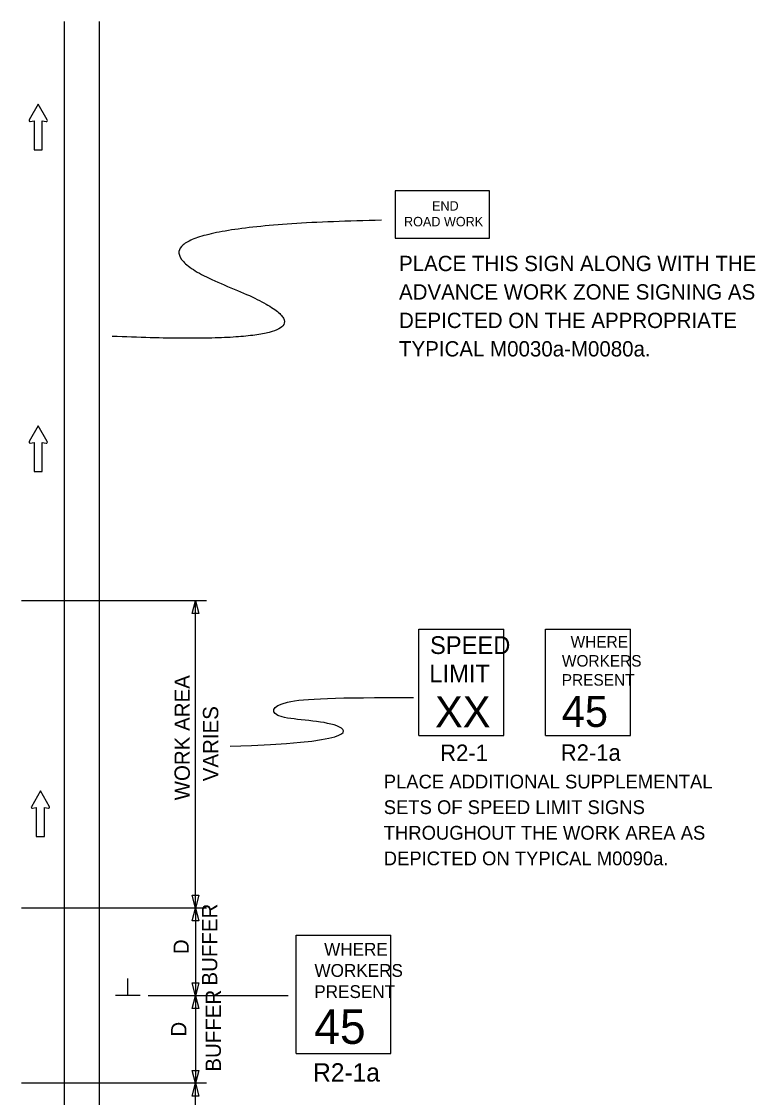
# Model space of a CAD drawing. Extents: x 16730 to 18475, y 5651 to 6927.
# Drawn here: x 17063.9 to 17399.4, y 6401.4 to 6893.1 of the extents above; entities that cross this region are included whole.
import ezdxf

# ---------------------------------------------------------------- set-up
doc = ezdxf.new("R2010")
doc.units = 0
for name, color, linetype in [('Level 6', 7, 'Continuous'), ('MT_SCRATCH_LEVEL_E', 7, 'Continuous'), ('PAVT_EDGE_EX', 7, 'Continuous'), ('TRAFFIC_SIGNS_PR', 7, 'Continuous'), ('TYPICAL_TEXT_DIMEN_PR', 7, 'Continuous')]:
    doc.layers.add(name, color=color, linetype=linetype)

msp = doc.modelspace()

# ---------------------------------------------------------------- linework, layer by layer
at = {"layer": 'Level 6'}
for p, q in [((17189.51, 6475.56), (17232.71, 6475.56)), ((17189.51, 6421.56), (17189.51, 6475.56)), ((17232.71, 6421.56), (17232.71, 6475.56)), ((17189.51, 6421.56), (17232.71, 6421.56))]:
    msp.add_line(p, q, dxfattribs=at)
at = {"layer": 'MT_SCRATCH_LEVEL_E'}
for p, q in [((17071.54, 6855.34), (17067.43, 6848.1)), ((17071.54, 6855.34), (17067.43, 6848.1)), ((17075.69, 6848.1), (17071.54, 6855.34)), ((17075.69, 6848.1), (17071.54, 6855.34)), ((17067.91, 6847.41), (17069.69, 6847.73)), ((17067.91, 6847.41), (17069.69, 6847.73)), ((17069.69, 6847.73), (17069.69, 6834.47)), ((17069.69, 6847.73), (17069.69, 6834.47)), ((17073.43, 6834.47), (17073.43, 6847.73)), ((17073.43, 6847.73), (17075.21, 6847.41)), ((17073.43, 6834.47), (17073.43, 6847.73)), ((17073.43, 6847.73), (17075.21, 6847.41)), ((17069.69, 6834.47), (17073.43, 6834.47)), ((17069.69, 6834.47), (17073.43, 6834.47)), ((17071.54, 6708.37), (17067.43, 6701.13)), ((17071.54, 6708.37), (17067.43, 6701.13)), ((17075.69, 6701.13), (17071.54, 6708.37)), ((17075.69, 6701.13), (17071.54, 6708.37)), ((17067.91, 6700.45), (17069.69, 6700.76)), ((17067.91, 6700.45), (17069.69, 6700.76)), ((17069.69, 6700.76), (17069.69, 6687.51)), ((17069.69, 6700.76), (17069.69, 6687.51)), ((17073.43, 6687.51), (17073.43, 6700.76)), ((17073.43, 6700.76), (17075.21, 6700.45)), ((17073.43, 6687.51), (17073.43, 6700.76)), ((17073.43, 6700.76), (17075.21, 6700.45)), ((17069.69, 6687.51), (17073.43, 6687.51)), ((17069.69, 6687.51), (17073.43, 6687.51)), ((17072.54, 6541.51), (17068.43, 6534.27)), ((17072.54, 6541.51), (17068.43, 6534.27)), ((17076.69, 6534.27), (17072.54, 6541.51)), ((17076.69, 6534.27), (17072.54, 6541.51)), ((17068.91, 6533.59), (17070.69, 6533.91)), ((17068.91, 6533.59), (17070.69, 6533.91)), ((17070.69, 6533.91), (17070.69, 6520.65)), ((17070.69, 6533.91), (17070.69, 6520.65)), ((17074.43, 6520.65), (17074.43, 6533.91)), ((17074.43, 6533.91), (17076.21, 6533.59)), ((17074.43, 6520.65), (17074.43, 6533.91)), ((17074.43, 6533.91), (17076.21, 6533.59)), ((17070.69, 6520.65), (17074.43, 6520.65)), ((17070.69, 6520.65), (17074.43, 6520.65))]:
    msp.add_line(p, q, dxfattribs=at)
for centre, start, end in [((17067.84, 6847.87), 150.4248, 279.9638), ((17067.84, 6847.87), 150.4248, 279.9638), ((17075.28, 6847.87), 260.0362, 29.7731), ((17075.28, 6847.87), 260.0362, 29.7731), ((17067.84, 6700.91), 150.4248, 279.9638), ((17067.84, 6700.91), 150.4248, 279.9638), ((17075.28, 6700.91), 260.0362, 29.7731), ((17075.28, 6700.91), 260.0362, 29.7731), ((17068.84, 6534.05), 150.4248, 279.9638), ((17068.84, 6534.05), 150.4248, 279.9638), ((17076.28, 6534.05), 260.0362, 29.7731), ((17076.28, 6534.05), 260.0362, 29.7731)]:
    msp.add_arc(centre, 0.463, start, end, dxfattribs=at)
at = {"layer": 'PAVT_EDGE_EX'}
for p, q in [((17083.43, 6893.09), (17083.43, 6095.81)), ((17099.43, 6893.09), (17099.43, 6095.81))]:
    msp.add_line(p, q, dxfattribs=at)
at = {"layer": 'TRAFFIC_SIGNS_PR'}
for p, q in [((17245.53, 6615.35), (17284.41, 6615.35)), ((17245.53, 6566.75), (17245.53, 6615.35)), ((17284.41, 6566.75), (17284.41, 6615.35)), ((17303.44, 6615.44), (17342.32, 6615.44)), ((17303.44, 6566.84), (17303.44, 6615.44)), ((17342.32, 6566.84), (17342.32, 6615.44)), ((17245.53, 6566.75), (17284.41, 6566.75)), ((17303.44, 6566.84), (17342.32, 6566.84))]:
    msp.add_line(p, q, dxfattribs=at)
msp.add_lwpolyline([(17234.69, 6794.16), (17277.89, 6794.16), (17277.89, 6815.76), (17234.69, 6815.76)], close=True, dxfattribs=at)
msp.add_open_spline([(17228.4, 6802.25), (17089.56, 6799.6), (17228.53, 6743.73), (17105.43, 6749.22)], degree=2, dxfattribs=at)
at = {"layer": 'TYPICAL_TEXT_DIMEN_PR'}
for p, q in [((17148.43, 6628.39), (17063.94, 6628.39)), ((17141.86, 6622.53), (17143.43, 6628.39)), ((17143.43, 6487.93), (17143.43, 6628.39)), ((17143.43, 6628.39), (17145, 6622.53)), ((17143.43, 6622.53), (17141.86, 6622.53)), ((17145, 6622.53), (17143.43, 6622.53)), ((17143.43, 6487.93), (17141.86, 6493.79)), ((17141.86, 6493.79), (17143.43, 6493.79)), ((17143.43, 6493.79), (17145, 6493.79)), ((17145, 6493.79), (17143.43, 6487.93)), ((17148.43, 6487.93), (17063.94, 6487.93)), ((17141.86, 6482.07), (17143.43, 6487.93)), ((17143.43, 6487.93), (17143.43, 6447.93)), ((17143.43, 6487.93), (17145, 6482.07)), ((17143.43, 6482.07), (17141.86, 6482.07)), ((17145, 6482.07), (17143.43, 6482.07)), ((17112.56, 6447.94), (17112.56, 6455.72)), ((17143.43, 6447.93), (17141.86, 6453.79)), ((17141.86, 6453.79), (17143.43, 6453.79)), ((17143.43, 6453.79), (17145, 6453.79)), ((17145, 6453.79), (17143.43, 6447.93)), ((17118.18, 6447.94), (17106.93, 6447.94)), ((17185.75, 6447.93), (17121.85, 6447.93)), ((17141.86, 6442.07), (17143.43, 6447.93)), ((17143.43, 6447.93), (17143.43, 6407.93)), ((17143.43, 6447.93), (17145, 6442.07)), ((17143.43, 6442.07), (17141.86, 6442.07)), ((17145, 6442.07), (17143.43, 6442.07)), ((17143.43, 6407.93), (17141.86, 6413.79)), ((17141.86, 6413.79), (17143.43, 6413.79)), ((17143.43, 6413.79), (17145, 6413.79)), ((17145, 6413.79), (17143.43, 6407.93)), ((17148.43, 6407.93), (17063.94, 6407.93)), ((17141.86, 6402.07), (17143.43, 6407.93)), ((17143.43, 6407.93), (17145, 6402.07)), ((17143.43, 6377.36), (17143.43, 6407.93)), ((17143.43, 6402.07), (17141.86, 6402.07)), ((17145, 6402.07), (17143.43, 6402.07))]:
    msp.add_line(p, q, dxfattribs=at)
msp.add_open_spline([(17159.29, 6561.95), (17215.11, 6563.58), (17214.13, 6573.73), (17176.29, 6573.73), (17178.8, 6583.48), (17207.53, 6584.17), (17243.13, 6584.19)], degree=3, dxfattribs=at)

# ---------------------------------------------------------------- texts
at = {"layer": 'Level 6'}
for s, height, p in [('45', 15.785, (17197.73, 6425.9)), ('R2-1a', 8.37, (17197.22, 6408.69))]:
    msp.add_text(s, height=height, dxfattribs=at).set_placement(p)
at = {"layer": 'TRAFFIC_SIGNS_PR'}
for s, height, p in [('END', 4.31, (17251.56, 6806.68)), ('ROAD WORK', 4.31, (17238.75, 6799.5)), ('PLACE THIS SIGN ALONG WITH THE', 7, (17236.47, 6779.02)), ('ADVANCE WORK ZONE SIGNING AS', 7, (17236.47, 6766.02)), ('DEPICTED ON THE APPROPRIATE', 7, (17236.47, 6753.02)), ('TYPICAL M0030a-M0080a.', 7, (17236.47, 6740.02)), ('SPEED', 8.1, (17250.62, 6604.07)), ('WHERE', 5.265, (17314.89, 6607.02)), ('WORKERS', 5.265, (17310.92, 6598.31)), ('LIMIT', 8.1, (17250.29, 6591.11)), ('PRESENT', 5.265, (17310.85, 6589.6)), ('XX', 14.206, (17252.93, 6570.55)), ('45', 14.206, (17310.84, 6570.74)), ('R2-1', 7.533, (17255.26, 6555.16)), ('R2-1a', 7.533, (17310.38, 6555.25)), ('PLACE ADDITIONAL SUPPLEMENTAL', 6.3, (17229.47, 6542.61)), ('SETS OF SPEED LIMIT SIGNS', 6.3, (17229.47, 6530.91)), ('THROUGHOUT THE WORK AREA AS', 6.3, (17229.47, 6519.21)), ('DEPICTED ON TYPICAL M0090a.', 6.3, (17229.47, 6507.51)), ('WHERE', 5.85, (17202.24, 6466.2)), ('WORKERS', 5.85, (17197.82, 6456.53)), ('PRESENT', 5.85, (17197.74, 6446.85))]:
    msp.add_text(s, height=height, dxfattribs=at).set_placement(p)
at = {"layer": 'TYPICAL_TEXT_DIMEN_PR'}
for s, p in [('WORK AREA', (17140.86, 6537.18)), ('VARIES', (17153.86, 6545.9)), ('BUFFER', (17153.4, 6452.53)), ('D', (17140.4, 6466.89)), ('BUFFER', (17155.07, 6413.2)), ('D', (17139.29, 6429.22))]:
    msp.add_text(s, height=7, rotation=90, dxfattribs=at).set_placement(p)

doc.saveas('drawing.dxf')
